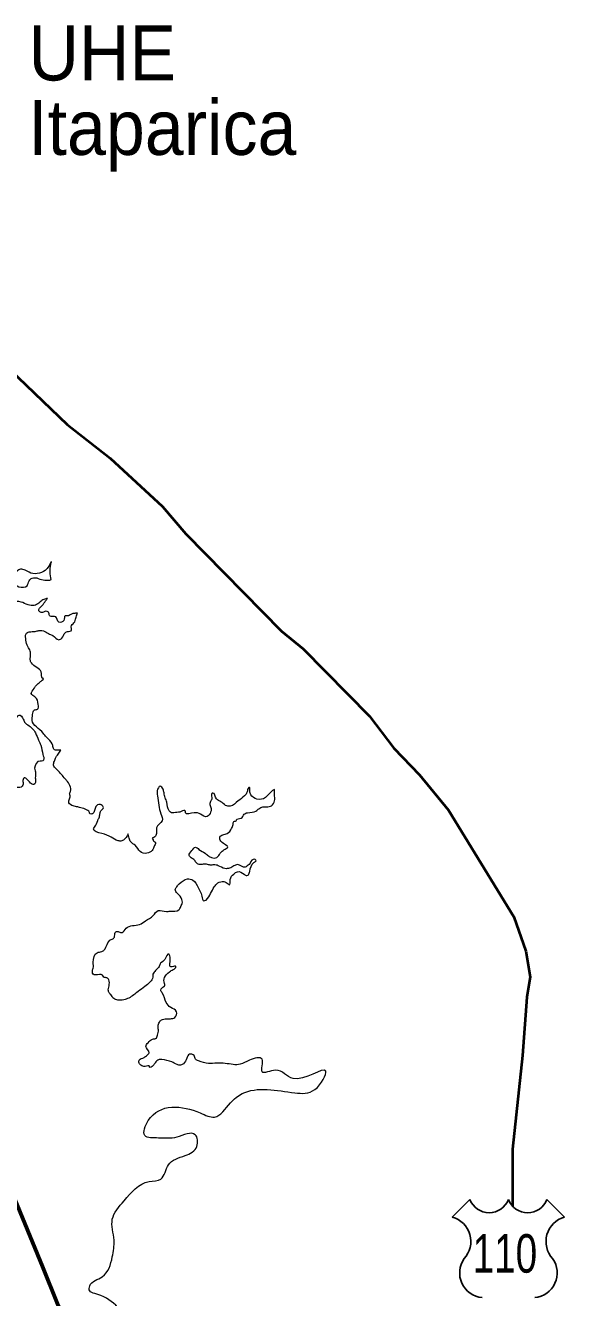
# Model space of a CAD drawing. Extents: x 553962 to 842807, y 8883888 to 9032388.
# Drawn here: x 579039 to 583934, y 8979171 to 8990726 of the extents above; entities that cross this region are included whole.
import ezdxf
from ezdxf.enums import TextEntityAlignment as Align

# ---------------------------------------------------------------- set-up
doc = ezdxf.new("R2010")
doc.units = 0
doc.header["$LTSCALE"] = 150
doc.linetypes.add('LONG_DASH_SHORT_DASH', pattern=[9.9, 6, -1.2, 1.5, -1.2])
for name, color, linetype, lineweight in [('12', 7, 'Continuous', 25), ('25', 7, 'Continuous', 13), ('48', 7, 'Continuous', 25), ('7', 7, 'LONG_DASH_SHORT_DASH', 60)]:
    doc.layers.add(name, color=color, linetype=linetype, lineweight=lineweight)
doc.layers.add('42', color=7, linetype='Continuous')

msp = doc.modelspace()

# ---------------------------------------------------------------- linework, layer by layer
at = {"layer": '12', "lineweight": 40}
msp.add_lwpolyline([(577759.9, 8988875.8), (577832.5, 8988674.7), (577901.5, 8988571.1), (578184.7, 8988310.3), (578513.4, 8987946.2), (578671.2, 8987814.3), (579419.2, 8987100.9), (579808.1, 8986794.1), (580283, 8986357.3), (580496.3, 8986108), (581364.8, 8985224.5), (581561.3, 8985062.5), (582162.5, 8984452.7), (582384.7, 8984161.9), (582616.4, 8983918.8), (582880.2, 8983596.7), (583472.4, 8982628.4), (583582.5, 8982317.7), (583621.7, 8982083.2), (583591.6, 8981897.8), (583552.5, 8981370), (583461.7, 8980518.1), (583461.7, 8980001.2)], dxfattribs=at)
at = {"layer": '25'}
msp.add_line((579360.2, 8984143), (579360.2, 8984143), dxfattribs=at)
for points in [[(579273.6, 8985691.7), (579262.6, 8985760.8), (579270.4, 8985832.5), (579275.2, 8985853.9), (579250.6, 8985814.9), (579184.7, 8985756.8), (579106.9, 8985746.5), (579036.1, 8985776.5), (578994.5, 8985786.4), (578962.1, 8985768.7), (578903.7, 8985717), (578869.8, 8985714.4), (578797.9, 8985729.3), (578742.4, 8985741.7), (578714.5, 8985761.7), (578707.6, 8985808.2), (578707.1, 8985839.7), (578702.8, 8985878.6), (578696.2, 8985903.7), (578709.8, 8985921.4), (578732.3, 8985927.7), (578766.7, 8985898.9), (578819, 8985842.5), (578840.5, 8985828.7), (578865.7, 8985831.3), (578882.9, 8985854), (578833.1, 8985911.7), (578787.2, 8985956.8), (578761.7, 8985989.4), (578753.7, 8986022.1), (578752, 8986049.7), (578760.5, 8986071.1), (578775.4, 8986088.8), (578774.1, 8986093.8), (578747.6, 8986095), (578707.5, 8986087.3), (578709, 8986071), (578678.5, 8986098.6), (578594.8, 8986151.1), (578625.6, 8986195.2), (578619, 8986220.3), (578556.1, 8986222.7), (578525.7, 8986238.9), (578514.1, 8986259), (578507.4, 8986286.6), (578469.8, 8986279), (578348.6, 8986320.1), (578316, 8986310), (578261.9, 8986311.1), (578227.7, 8986334.8), (578211.8, 8986392.6), (578200, 8986424), (578182.2, 8986445.3), (578162.1, 8986442.8), (578137.4, 8986408.8), (578076.6, 8986445), (578015.8, 8986477.6), (577903.1, 8986532.5), (577871.5, 8986547.5), (577847.3, 8986571.3), (577798.2, 8986577.5), (577769.1, 8986588.7), (577762.6, 8986601.3), (577791.1, 8986635.3), (577830.8, 8986673.1), (577847.9, 8986707.1), (577881.3, 8986751.2), (577915.6, 8986814.2), (577920.5, 8986825.5), (577912.8, 8986834.3), (577832.1, 8986761.1), (577791.2, 8986718.3), (577750.2, 8986684.2), (577700.5, 8986642.6), (577655.4, 8986628.6), (577607.2, 8986657.4), (577600.7, 8986678.7), (577572.9, 8986687.5), (577531.5, 8986682.3), (577497.5, 8986683.5), (577418, 8986707.1), (577317.8, 8986770.9), (577294.8, 8986796), (577260.4, 8986828.6), (577233.5, 8986870), (577208.6, 8986939.1), (577217.8, 8987002), (577178.5, 8987030.8), (577145.3, 8987065.9), (577133.7, 8987086), (577145.8, 8987117.4)], [(579238.3, 8985520.6), (579223.2, 8985518.1), (579188.2, 8985501.6), (579159.6, 8985477.6), (579118.4, 8985457.4), (579063, 8985463.5), (578998.6, 8985488.5), (578918.1, 8985487), (578890.3, 8985471.6), (578828.3, 8985436.4), (578783.6, 8985398.6), (578744.5, 8985409.8), (578712.6, 8985439.8), (578712, 8985481.3), (578710.1, 8985534.1), (578741.9, 8985595.8), (578773.2, 8985608.5), (578833.9, 8985584.4), (578866.5, 8985586.2), (578887.3, 8985626.4), (578918.5, 8985646.7), (578980.3, 8985628), (579053.1, 8985635.7), (579072.6, 8985682.3), (579099.9, 8985706.3), (579214.6, 8985686.5), (579237.2, 8985686.6), (579259.8, 8985687.9), (579273.6, 8985691.7)], [(579511.6, 8985388.2), (579477.7, 8985384.3), (579450.2, 8985375.4), (579422.9, 8985361.7), (579398.8, 8985363.9), (579388.1, 8985321.2), (579343, 8985305.9), (579313.5, 8985353.6), (579290.8, 8985357.3), (579258, 8985364.8), (579247.5, 8985397.4), (579224.8, 8985404.9), (579182.2, 8985393.5), (579161.8, 8985408.5), (579188.9, 8985455.1), (579221, 8985497.9), (579238.3, 8985520.6)], [(579360.2, 8984143), (579331.3, 8984141.7), (579297.2, 8984151.6), (579286.7, 8984185.5), (579249.5, 8984242), (579213.8, 8984278.4), (579199.7, 8984297.2), (579098.8, 8984413.8), (579104.3, 8984465.4), (579120.1, 8984508.2), (579148.9, 8984515.8), (579155.9, 8984557.3), (579124.8, 8984626.4), (579091.7, 8984656.4), (579117.4, 8984704.3), (579135.9, 8984730.8), (579173.2, 8984762.3), (579190.6, 8984778.7), (579201.7, 8984792.6), (579197.9, 8984795.1), (579182, 8984854.1), (579141.2, 8984893), (579092.9, 8984935.6), (579082.4, 8984964.4), (579084.5, 8984997.1), (579084.5, 8984998.4), (579082.6, 8985043.7), (579062, 8985083.8), (579042.3, 8985141.6), (579040.6, 8985173), (579044, 8985199.4), (579074, 8985217.1), (579126.7, 8985222.3), (579161.8, 8985230), (579214.7, 8985221.3), (579257.8, 8985196.3), (579288.1, 8985183.8), (579341.4, 8985146.3), (579370.2, 8985160.2), (579399.7, 8985209.3), (579429.7, 8985222), (579453.5, 8985227.1), (579457.8, 8985276.1), (579471.5, 8985290), (579494.8, 8985332.8), (579505.6, 8985371.8), (579511.6, 8985388.2)], [(578322.2, 8984298.3), (578358.7, 8984292.2), (578427.7, 8984303.7), (578468.3, 8984278.7), (578508.1, 8984306.4), (578553.9, 8984359.4), (578612.5, 8984393.5), (578650, 8984408.7), (578681.5, 8984410.1), (578739.7, 8984376.3), (578782.7, 8984361.3), (578826.6, 8984371.5), (578848.7, 8984404.3), (578866.2, 8984411.9), (578909, 8984413.2), (578934.1, 8984412.1), (578960.1, 8984439.8), (578981.2, 8984461.2), (579019.4, 8984423.6), (579036.2, 8984389.7), (579060.4, 8984372.2), (579130.5, 8984299.5), (579156.6, 8984234.2), (579178.6, 8984187.7), (579197.3, 8984104.8), (579203, 8984053.3), (579196.9, 8984044.5), (579173, 8984044.4), (579122.3, 8983978.9), (579130.5, 8983933.6), (579128.5, 8983892.1), (579129.2, 8983848.1), (579115.5, 8983831.7), (579085.2, 8983844.2), (579049.5, 8983883.1), (579033, 8983893.1), (579015.8, 8983866.6), (579018.7, 8983834), (578989, 8983803.7), (578942.3, 8983816.1), (578886.3, 8983860), (578807.1, 8983956.6), (578786.5, 8983987.9), (578752.4, 8983999.1), (578750, 8983997.9), (578761.1, 8983917.4), (578797.5, 8983829.5), (578838.7, 8983756.7), (578879.6, 8983709.1), (578895, 8983686.5), (578904.1, 8983663.9), (578849.1, 8983639.8), (578774.6, 8983663.5), (578713.9, 8983693.5), (578683.2, 8983734.9), (578661.2, 8983773.8), (578642.4, 8983770), (578624.6, 8983698.3), (578609.7, 8983679.4), (578545.6, 8983680.4), (578416.9, 8983712.7), (578385.3, 8983725.2), (578407.5, 8983755.5), (578439.5, 8983805.8), (578432.9, 8983832.2), (578371.3, 8983829.5), (578327.3, 8983830.7), (578280.4, 8983862), (578257.6, 8983874.5), (578235.2, 8983855.5), (578206.5, 8983839.1), (578166.4, 8983827.7), (578128, 8983879.1), (578073, 8983948.1), (578033.4, 8983997), (577995.2, 8984028.3), (577983.5, 8984057.2), (577976.9, 8984079.8), (577990.5, 8984101.2), (578044.8, 8984081.3), (578086.8, 8984039.9), (578136, 8984033.8), (578156, 8984037.6), (578188.7, 8984041.5)], [(578322.2, 8984298.3), (578358.7, 8984292.2), (578427.7, 8984303.7), (578468.3, 8984278.7), (578508.1, 8984306.4), (578553.9, 8984359.4), (578612.5, 8984393.5), (578650, 8984408.7), (578681.5, 8984410.1), (578739.7, 8984376.3), (578782.7, 8984361.3), (578826.6, 8984371.5), (578848.7, 8984404.3), (578866.2, 8984411.9), (578909, 8984413.2), (578934.1, 8984412.1), (578960.1, 8984439.8), (578981.2, 8984461.2), (579019.4, 8984423.6), (579036.2, 8984389.7), (579060.4, 8984372.2), (579130.5, 8984299.5), (579156.6, 8984234.2), (579178.6, 8984187.7), (579197.3, 8984104.8), (579203, 8984053.3), (579196.9, 8984044.5), (579173, 8984044.4), (579122.3, 8983978.9), (579130.5, 8983933.6), (579128.5, 8983892.1), (579129.2, 8983848.1), (579115.5, 8983831.7), (579085.2, 8983844.2), (579049.5, 8983883.1), (579033, 8983893.1), (579015.8, 8983866.6), (579018.7, 8983834), (578989, 8983803.7), (578942.3, 8983816.1), (578886.3, 8983860), (578807.1, 8983956.6), (578786.5, 8983987.9), (578752.4, 8983999.1), (578750, 8983997.9), (578761.1, 8983917.4), (578797.5, 8983829.5), (578838.7, 8983756.7), (578879.6, 8983709.1), (578895, 8983686.5), (578904.1, 8983663.9), (578849.1, 8983639.8), (578774.6, 8983663.5), (578713.9, 8983693.5), (578683.2, 8983734.9), (578661.2, 8983773.8), (578642.4, 8983770), (578624.6, 8983698.3), (578609.7, 8983679.4), (578545.6, 8983680.4), (578416.9, 8983712.7), (578385.3, 8983725.2), (578407.5, 8983755.5), (578439.5, 8983805.8), (578432.9, 8983832.2), (578371.3, 8983829.5), (578327.3, 8983830.7), (578280.4, 8983862), (578257.6, 8983874.5), (578235.2, 8983855.5), (578206.5, 8983839.1), (578166.4, 8983827.7), (578128, 8983879.1), (578073, 8983948.1), (578033.4, 8983997), (577995.2, 8984028.3), (577983.5, 8984057.2), (577976.9, 8984079.8), (577990.5, 8984101.2), (578044.8, 8984081.3), (578086.8, 8984039.9), (578136, 8984033.8), (578156, 8984037.6), (578188.7, 8984041.5)], [(579970.3, 8983381.7), (579928.3, 8983326.2), (579913.3, 8983318.6), (579880.6, 8983319.8), (579816, 8983353.5), (579732.6, 8983386), (579656.6, 8983427.2), (579677.5, 8983461.2), (579700.7, 8983516.6), (579706.8, 8983528), (579715.1, 8983564.5), (579723.5, 8983590.9), (579747, 8983622.4), (579727.8, 8983646.2), (579713.9, 8983650), (579679, 8983632.2), (579647.2, 8983565.5), (579623.3, 8983566.7), (579619.4, 8983578), (579581.3, 8983606.8), (579528.2, 8983623), (579513.1, 8983626.7), (579471.5, 8983636.7), (579433.4, 8983665.5), (579440.4, 8983701.9), (579442.4, 8983737.2), (579441.2, 8983739.7), (579447, 8983768.6), (579413, 8983867.8), (579391.3, 8983892.9), (579318.5, 8983971.9), (579294.2, 8984005.8), (579301.2, 8984042.2), (579315.8, 8984077.5), (579343, 8984115.3), (579355.3, 8984132.9), (579360.2, 8984143)], [(580290.3, 8983788.7), (580262.3, 8983816.3), (580235.2, 8983772.2), (580237.1, 8983729.5), (580249.6, 8983642.7), (580269.5, 8983564.8), (580280.4, 8983502), (580228.5, 8983437.7), (580228.9, 8983411.3), (580225.6, 8983377.4), (580205.8, 8983349.7), (580190.8, 8983343.3), (580198.6, 8983327), (580199.9, 8983323.2), (580212.7, 8983309.5), (580216.4, 8983308.2), (580211.9, 8983275.5), (580188.6, 8983232.7), (580142.4, 8983206.2), (580080.6, 8983222.3), (580035.8, 8983278.8), (579995.2, 8983308.8), (579980.9, 8983344), (579975.5, 8983366.6), (579970.3, 8983381.7)], [(581134, 8983136.2), (581123.8, 8983150.6), (581105.6, 8983150.6), (581070.3, 8983105.8), (581052.9, 8983091.9), (581034.2, 8983079.3), (580963.5, 8983103), (580932.2, 8983091.6), (580892.3, 8983071.3), (580850.8, 8983067.4), (580790.1, 8983093.7), (580748.6, 8983101.1), (580717.2, 8983098.5), (580683.1, 8983107.2), (580642.9, 8983105.8), (580622.8, 8983104.5), (580595, 8983115.7), (580573.2, 8983143.3), (580544, 8983165.8), (580526.1, 8983187.2), (580550.7, 8983231.2), (580582.9, 8983261.5), (580614.6, 8983241.5), (580670.4, 8983206.5), (580700.9, 8983182.7), (580728.8, 8983167.7), (580775.3, 8983167.8), (580800.1, 8983195.5), (580833.5, 8983232.1), (580860.9, 8983248.5), (580877.1, 8983263.7), (580868.1, 8983274.9), (580826.2, 8983303.7), (580804.4, 8983335.1), (580804.2, 8983354), (580830.3, 8983372.9), (580870.4, 8983385.6), (580911.2, 8983432.2), (580924.6, 8983468.7), (580931.7, 8983493.9), (580954.2, 8983506.5), (580954.2, 8983507.8), (580996.7, 8983524.3), (581025.1, 8983560.8), (581056.3, 8983574.7), (581131.6, 8983588.8), (581158.9, 8983611.5), (581195.2, 8983628), (581227.9, 8983628), (581273, 8983638.2), (581301.3, 8983683.6), (581303.5, 8983703.7), (581299.1, 8983749), (581299.9, 8983784.2), (581260.8, 8983756), (581236.5, 8983729.9), (581217.9, 8983712.2), (581141.4, 8983698.2), (581085.5, 8983738.3), (581076.3, 8983772.2), (581072.1, 8983803.6), (581068.3, 8983802.3), (581051.3, 8983763.3), (581027.9, 8983726.8), (580969.4, 8983681.3), (580898.4, 8983634.6), (580856.8, 8983640.8), (580813.6, 8983674.6), (580774.3, 8983699.6), (580739.6, 8983752.3), (580732.1, 8983748.5), (580731.6, 8983699.5), (580718.1, 8983675.6), (580716, 8983641.6), (580725.3, 8983605.2), (580720.6, 8983578.8), (580689.7, 8983539.7), (580627.8, 8983560.9), (580572.3, 8983574.6), (580493.2, 8983574.3), (580490.4, 8983591.9), (580477.8, 8983595.6), (580476.5, 8983595.6), (580454, 8983585.5), (580401.3, 8983576.6), (580373.7, 8983572.7), (580343.3, 8983592.7), (580322.1, 8983669.4), (580307.7, 8983710.8), (580297.1, 8983754.8), (580290.3, 8983788.7)], [(579888.2, 8982493.8), (579915.9, 8982486.3), (579954.3, 8982525.4), (580074.6, 8982559.7), (580129.7, 8982594), (580199.2, 8982640.5), (580243.8, 8982685.9), (580319.4, 8982677.4), (580352, 8982681.2), (580431.1, 8982691.5), (580449.5, 8982723), (580464.1, 8982760.8), (580459.9, 8982787.2), (580418.9, 8982842.4), (580399.6, 8982877.5), (580413.1, 8982902.7), (580435.4, 8982927.9), (580511.4, 8982973.4), (580556.8, 8982964.7), (580606.8, 8982894.5), (580640.6, 8982816.6), (580660, 8982773.9), (580678.8, 8982781.5), (580720.7, 8982842), (580753.8, 8982901.2), (580786, 8982936.5), (580839.9, 8982949.2), (580880.4, 8982928), (580889.3, 8982920.5), (580898.7, 8982967), (580930.7, 8983017.4), (580964.4, 8983038.9), (581023.8, 8983016.4), (581049.1, 8983003.9), (581064.1, 8983011.5), (581075, 8983041.7), (581112.8, 8983122.3), (581134, 8983136.2)], [(580701.6, 8981295.5), (580609.5, 8981320.4), (580584.1, 8981335.4), (580569.8, 8981369.3), (580528.2, 8981380.5), (580503.6, 8981343.9), (580472.8, 8981294.8), (580447.8, 8981282.2), (580415.1, 8981287.1), (580367, 8981310.8), (580278.7, 8981332), (580253.6, 8981331.9), (580216.2, 8981301.6), (580199, 8981278.9), (580166.5, 8981262.5), (580166.4, 8981268.8), (580124.9, 8981269.9), (580087, 8981282.4), (580067.8, 8981308.7), (580071.3, 8981326.3), (580116.2, 8981351.6), (580143.6, 8981371.8), (580160.9, 8981394.5), (580132.5, 8981452.2), (580152.1, 8981485), (580191.9, 8981517.8), (580212, 8981521.6), (580220.8, 8981522.9), (580239.2, 8981553.1), (580246.1, 8981602.2), (580243.1, 8981637.4), (580255.2, 8981671.3), (580273.8, 8981692.8), (580318.9, 8981701.7), (580355.3, 8981703.1), (580396.6, 8981715.8), (580411, 8981767.4), (580357.7, 8981806.2), (580318.1, 8981851.3), (580280.5, 8981938), (580268.8, 8981964.3), (580279.8, 8981983.2), (580304.7, 8982007.2), (580300.7, 8982023.5), (580301.2, 8982078.8), (580347, 8982129.3), (580379.4, 8982149.5), (580399.3, 8982162.1), (580405.4, 8982177.2), (580371.5, 8982174.6), (580352.6, 8982177.1), (580351, 8982206), (580351.8, 8982233.6), (580344.8, 8982286.4), (580341, 8982290.2), (580305.2, 8982242.3), (580266.7, 8982207), (580252, 8982179.3), (580221.1, 8982140.2), (580196.4, 8982107.5), (580194.3, 8982079.8), (580171, 8982037), (580122.5, 8981996.6), (580061.6, 8981949.9), (580021.7, 8981919.6), (579976.9, 8981890.6), (579931.8, 8981875.3), (579877.8, 8981872.7), (579841.2, 8981886.4), (579814.3, 8981922.8), (579804.1, 8981932.8), (579792.4, 8981955.4), (579798.1, 8982001.9), (579794.8, 8982057.2), (579778.2, 8982074.8), (579751.8, 8982079.7), (579738.9, 8982098.6), (579674.8, 8982100.9), (579653.3, 8982109.6), (579649, 8982146.1), (579653.8, 8982162.4), (579654.3, 8982216.5), (579689.6, 8982303.3), (579732.2, 8982313.5), (579754.6, 8982328.7), (579781.6, 8982379.1), (579817.5, 8982423.2), (579832.5, 8982428.2), (579848.5, 8982453.4), (579859.3, 8982492.4), (579888.2, 8982493.8)], [(581113.2, 8977420.6), (581052, 8977586.8), (581044.4, 8977701), (581112.9, 8977822.7), (581219.3, 8977944.5), (581226.9, 8977959.7), (581325.8, 8977997.7), (581150.9, 8978172.7), (581059.6, 8978180.3), (580846.7, 8978073.8), (580823.9, 8977997.7), (580687, 8978020.5), (580474.1, 8978324.9), (580542.6, 8978644.5), (580633.8, 8978751), (580808.7, 8978933.6), (580808.7, 8978941.2), (580763.1, 8978956.4), (580603.4, 8978888), (580382.9, 8978773.8), (580109.1, 8978811.9), (579858.2, 8979101), (579668.1, 8979207.5), (579622.5, 8979230.4), (579622.5, 8979276), (579736.5, 8979359.7), (579827.8, 8979539.3), (579843, 8979691.5), (579827.8, 8979881.7), (579934.2, 8980049.1), (580162.3, 8980224.1), (580268.8, 8980246.9), (580337.2, 8980376.3), (580489.3, 8980460), (580595.8, 8980543.7), (580580.6, 8980650.2), (580413.3, 8980627.4), (580246, 8980619.8), (580124.3, 8980642.6), (580154.7, 8980779.6), (580626.2, 8980848), (580755.5, 8980810), (580899.9, 8980939.3), (581006.4, 8981023), (581485.5, 8981030.6), (581667.9, 8981061.1), (581765.3, 8981228.5), (581468.7, 8981160), (581309, 8981236.1), (581187.4, 8981220.9), (581187.4, 8981335), (581073.3, 8981327.4), (580989.7, 8981289.3), (580852.8, 8981297), (580701.6, 8981295.5)]]:
    msp.add_spline(points, degree=3, dxfattribs=at)
at = {"layer": '48'}
for p, q in [((582914.9, 8979901.3), (583074.8, 8980061.2)), ((583774.1, 8980061.2), (583934.1, 8979901.3))]:
    msp.add_line(p, q, dxfattribs=at)
for centre, radius, start, end in [((583249.6, 8980128.1), 187.2, 200.95927, 339.04073), ((583599.3, 8980128.1), 187.2, 200.95927, 339.04073), ((582852.8, 8979679.4), 230.3, 317.5721, 74.36886), ((583996.1, 8979679.4), 230.3, 105.62774, 222.4279), ((583206.3, 8979394.3), 224.7, 144.73733, 264.65778), ((583642.6, 8979394.3), 224.7, 275.34222, 35.26267)]:
    msp.add_arc(centre, radius, start, end, dxfattribs=at)
at = {"layer": '7'}
msp.add_line((579193.1, 8979451.5), (578797.8, 8980419.1), dxfattribs=at)
msp.add_lwpolyline([(579193.1, 8979451.5), (579330.6, 8979113.2), (579479.8, 8978793), (579620.2, 8978538.1), (579698.1, 8978330.6), (580056.8, 8977617.4), (580139.1, 8977491.6), (580748.7, 8976177.5), (580932.4, 8975835.9), (581202.8, 8975191.5), (581475, 8974750.7), (581628.9, 8974447.2), (581670.5, 8974336.1)], dxfattribs=at)

# ---------------------------------------------------------------- texts
at = {"layer": '42', "width": 0.95}
for s, p in [('UHE', (579736.7, 8990226.1)), ('Itaparica', (580281.3, 8989550))]:
    msp.add_text(s, height=500, dxfattribs=at).set_placement(p, align=Align.CENTER)
at = {"layer": '48', "width": 0.75}
msp.add_text('110', height=350, dxfattribs=at).set_placement((583392.5, 8979396.6), align=Align.CENTER)

doc.saveas('drawing.dxf')
